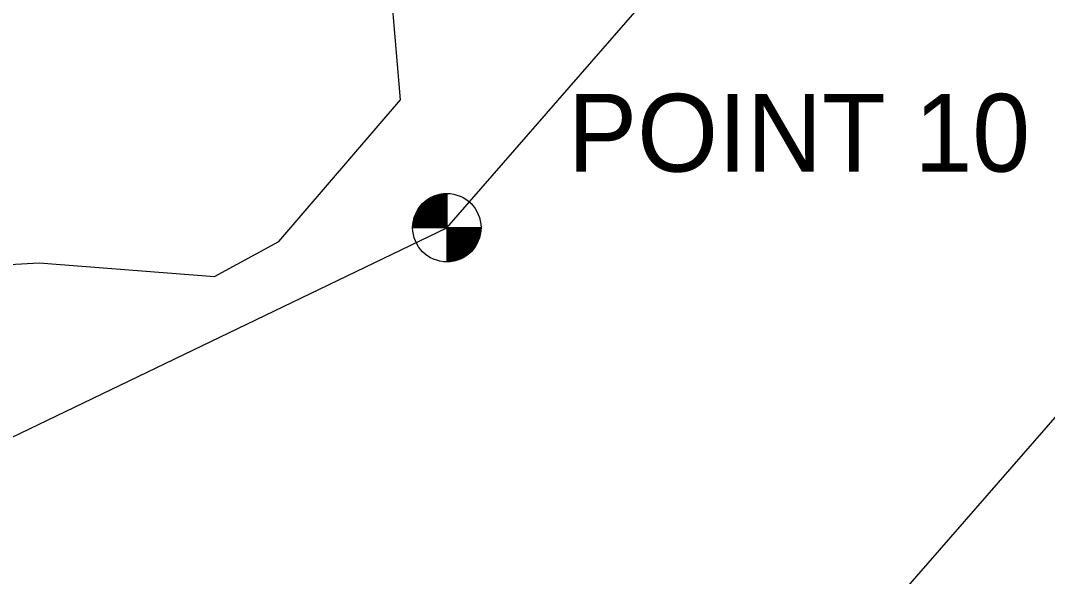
# Model space of a CAD drawing. Extents: x 2091245 to 2092168, y 863656 to 864307.
# Drawn here: x 2091682 to 2091734.8, y 863917.6 to 863946.2 of the extents above; entities that cross this region are included whole.
import ezdxf

# ---------------------------------------------------------------- set-up
doc = ezdxf.new("R2010")
doc.units = 0
for name, color, linetype in [('Exist Hydro Jurisdictional Stream or Body of Water', 7, 'Continuous'), ('Exist Hydrographic Top of Bank', 7, 'Continuous'), ('Prop Boundary Buffer Zone 1', 7, 'Continuous'), ('Prop Boundary Buffer Zone 2', 7, 'Continuous'), ('Scratch_Level_6', 7, 'Continuous')]:
    doc.layers.add(name, color=color, linetype=linetype)

msp = doc.modelspace()

# ---------------------------------------------------------------- linework, layer by layer
at = {"layer": 'Exist Hydro Jurisdictional Stream or Body of Water'}
msp.add_lwpolyline([(2091673.038, 863927.911), (2091672.627, 863930.924), (2091675.297, 863933.324), (2091682.95, 863933.761), (2091691.963, 863933.051), (2091695.28, 863934.846), (2091701.524, 863942.139), (2091700.79, 863950.834), (2091700.072, 863952.463), (2091701.052, 863960.667), (2091705.84, 863965.844), (2091716.038, 863968.921), (2091730.163, 863972.743), (2091727.795, 863981.975), (2091728.219, 863990.873), (2091752.896, 864007.718), (2091756.927, 864019.571), (2091767.092, 864026.792), (2091774.676, 864028.045), (2091779.207, 864034.48), (2091785.465, 864035.877), (2091790.325, 864037.563), (2091800.277, 864042.765), (2091802.985, 864045.288)], dxfattribs=at)
at = {"layer": 'Exist Hydrographic Top of Bank'}
msp.add_lwpolyline([(2091672.3, 863948.34), (2091672.795, 863927.55), (2091675.886, 863922.062), (2091703.915, 863935.563), (2091732.111, 863967.919), (2091742.84, 863995.86), (2091771.423, 864017.904), (2091796.939, 864035.122), (2091802.35, 864043.97), (2091798.347, 864050.35), (2091774.513, 864034.247), (2091751.1, 864019.64), (2091722.53, 863989.28), (2091717.91, 863987.56), (2091701.99, 863966.43)], close=True, dxfattribs=at)
at = {"layer": 'Prop Boundary Buffer Zone 1'}
msp.add_lwpolyline([(2091641.896, 863964.945), (2091642.981, 863919.351), (2091663.555, 863882.824), (2091722.485, 863911.209), (2091758.215, 863952.211), (2091767.828, 863977.246), (2091788.992, 863993.568), (2091819.128, 864013.904), (2091837.639, 864044.171), (2091807.267, 864092.583), (2091758.17, 864059.411), (2091731.919, 864043.033), (2091705.49, 864014.948), (2091699.226, 864012.616), (2091681.482, 863989.064)], close=True, dxfattribs=at)
at = {"layer": 'Prop Boundary Buffer Zone 2'}
msp.add_lwpolyline([(2091688.904, 863895.034), (2091722.485, 863911.209), (2091758.215, 863952.211), (2091767.828, 863977.246), (2091788.992, 863993.568), (2091813.72, 864010.255)], dxfattribs=at)
at = {"layer": 'Scratch_Level_6'}
for p, q in [((2091702.158, 863935.597), (2091703.881, 863937.32)), ((2091702.159, 863935.633), (2091703.845, 863937.319)), ((2091702.16, 863935.563), (2091703.915, 863937.319)), ((2091702.161, 863935.67), (2091703.808, 863937.317)), ((2091702.164, 863935.708), (2091703.77, 863937.314)), ((2091702.167, 863935.748), (2091703.731, 863937.311)), ((2091702.172, 863935.788), (2091703.691, 863937.306)), ((2091702.178, 863935.829), (2091703.649, 863937.3)), ((2091702.185, 863935.871), (2091703.607, 863937.293)), ((2091702.193, 863935.915), (2091703.564, 863937.285)), ((2091702.195, 863935.563), (2091703.915, 863937.283)), ((2091702.203, 863935.96), (2091703.518, 863937.275)), ((2091702.214, 863936.007), (2091703.471, 863937.263)), ((2091702.228, 863936.056), (2091703.422, 863937.25)), ((2091702.23, 863935.563), (2091703.915, 863937.248)), ((2091702.244, 863936.107), (2091703.371, 863937.234)), ((2091702.262, 863936.161), (2091703.317, 863937.216)), ((2091702.266, 863935.563), (2091703.915, 863937.213)), ((2091702.284, 863936.218), (2091703.26, 863937.194)), ((2091702.301, 863935.563), (2091703.915, 863937.177)), ((2091702.31, 863936.279), (2091703.199, 863937.168)), ((2091702.336, 863935.563), (2091703.915, 863937.142)), ((2091702.342, 863936.346), (2091703.132, 863937.136)), ((2091702.372, 863935.563), (2091703.915, 863937.106)), ((2091702.382, 863936.421), (2091703.057, 863937.097)), ((2091702.407, 863935.563), (2091703.915, 863937.071)), ((2091702.434, 863936.509), (2091702.969, 863937.044)), ((2091702.442, 863935.563), (2091703.915, 863937.036)), ((2091702.478, 863935.563), (2091703.915, 863937)), ((2091702.896, 863936.995), (2091703.915, 863935.976)), ((2091702.917, 863937.01), (2091703.915, 863936.012)), ((2091702.938, 863937.024), (2091703.915, 863936.047)), ((2091702.959, 863937.038), (2091703.915, 863936.082)), ((2091702.981, 863937.052), (2091703.915, 863936.118)), ((2091703.003, 863937.065), (2091703.915, 863936.153)), ((2091703.025, 863937.079), (2091703.915, 863936.188)), ((2091703.048, 863937.091), (2091703.915, 863936.224)), ((2091703.07, 863937.104), (2091703.915, 863936.259)), ((2091703.093, 863937.116), (2091703.915, 863936.295)), ((2091703.116, 863937.129), (2091703.915, 863936.33)), ((2091703.14, 863937.14), (2091703.915, 863936.365)), ((2091703.164, 863937.152), (2091703.915, 863936.401)), ((2091703.188, 863937.163), (2091703.915, 863936.436)), ((2091703.213, 863937.174), (2091703.915, 863936.471)), ((2091703.237, 863937.185), (2091703.915, 863936.507)), ((2091703.262, 863937.195), (2091703.915, 863936.542)), ((2091703.288, 863937.205), (2091703.915, 863936.577)), ((2091703.314, 863937.214), (2091703.915, 863936.613)), ((2091703.34, 863937.224), (2091703.915, 863936.648)), ((2091703.366, 863937.233), (2091703.915, 863936.683)), ((2091703.393, 863937.241), (2091703.915, 863936.719)), ((2091703.42, 863937.249), (2091703.915, 863936.754)), ((2091703.447, 863937.257), (2091703.915, 863936.79)), ((2091703.475, 863937.265), (2091703.915, 863936.825)), ((2091703.504, 863937.272), (2091703.915, 863936.86)), ((2091703.532, 863937.278), (2091703.915, 863936.896)), ((2091703.561, 863937.285), (2091703.915, 863936.931)), ((2091703.591, 863937.29), (2091703.915, 863936.966)), ((2091703.621, 863937.296), (2091703.915, 863937.002)), ((2091703.652, 863937.301), (2091703.915, 863937.037)), ((2091703.682, 863937.305), (2091703.915, 863937.072)), ((2091703.714, 863937.309), (2091703.915, 863937.108)), ((2091703.746, 863937.312), (2091703.915, 863937.143)), ((2091703.778, 863937.315), (2091703.915, 863937.178)), ((2091703.811, 863937.317), (2091703.915, 863937.214)), ((2091703.845, 863937.319), (2091703.915, 863937.249)), ((2091703.88, 863937.32), (2091703.915, 863937.284)), ((2091703.914, 863937.321), (2091703.915, 863937.32)), ((2091703.915, 863937.321), (2091703.915, 863933.805)), ((2091702.418, 863936.484), (2091703.339, 863935.563)), ((2091702.432, 863936.505), (2091703.374, 863935.563)), ((2091702.446, 863936.527), (2091703.409, 863935.563)), ((2091702.46, 863936.548), (2091703.445, 863935.563)), ((2091702.474, 863936.569), (2091703.48, 863935.563)), ((2091702.489, 863936.59), (2091703.515, 863935.563)), ((2091702.504, 863936.61), (2091703.551, 863935.563)), ((2091702.513, 863935.563), (2091703.915, 863936.965)), ((2091702.516, 863936.626), (2091702.852, 863936.962)), ((2091702.519, 863936.63), (2091703.586, 863935.563)), ((2091702.534, 863936.65), (2091703.621, 863935.563)), ((2091702.548, 863935.563), (2091703.915, 863936.93)), ((2091702.55, 863936.67), (2091703.657, 863935.563)), ((2091702.566, 863936.689), (2091703.692, 863935.563)), ((2091702.582, 863936.708), (2091703.728, 863935.563)), ((2091702.584, 863935.563), (2091703.915, 863936.894)), ((2091702.599, 863936.727), (2091703.763, 863935.563)), ((2091702.615, 863936.746), (2091703.798, 863935.563)), ((2091702.619, 863935.563), (2091703.915, 863936.859)), ((2091702.632, 863936.764), (2091703.834, 863935.563)), ((2091702.649, 863936.782), (2091703.869, 863935.563)), ((2091702.655, 863935.563), (2091703.915, 863936.824)), ((2091702.667, 863936.8), (2091703.904, 863935.563)), ((2091702.685, 863936.818), (2091703.915, 863935.587)), ((2091702.69, 863935.563), (2091703.915, 863936.788)), ((2091702.703, 863936.835), (2091703.915, 863935.623)), ((2091702.721, 863936.852), (2091703.915, 863935.658)), ((2091702.725, 863935.563), (2091703.915, 863936.753)), ((2091702.739, 863936.869), (2091703.915, 863935.693)), ((2091702.758, 863936.886), (2091703.915, 863935.729)), ((2091702.761, 863935.563), (2091703.915, 863936.718)), ((2091702.777, 863936.902), (2091703.915, 863935.764)), ((2091702.796, 863936.918), (2091703.915, 863935.8)), ((2091702.796, 863935.563), (2091703.915, 863936.682)), ((2091702.816, 863936.934), (2091703.915, 863935.835)), ((2091702.831, 863935.563), (2091703.915, 863936.647)), ((2091702.836, 863936.95), (2091703.915, 863935.87)), ((2091702.856, 863936.965), (2091703.915, 863935.906)), ((2091702.867, 863935.563), (2091703.915, 863936.612)), ((2091702.876, 863936.98), (2091703.915, 863935.941)), ((2091702.902, 863935.563), (2091703.915, 863936.576)), ((2091702.937, 863935.563), (2091703.915, 863936.541)), ((2091702.973, 863935.563), (2091703.915, 863936.505)), ((2091703.008, 863935.563), (2091703.915, 863936.47)), ((2091702.202, 863935.957), (2091702.596, 863935.563)), ((2091702.209, 863935.985), (2091702.631, 863935.563)), ((2091702.216, 863936.014), (2091702.667, 863935.563)), ((2091702.224, 863936.041), (2091702.702, 863935.563)), ((2091702.232, 863936.069), (2091702.738, 863935.563)), ((2091702.24, 863936.096), (2091702.773, 863935.563)), ((2091702.249, 863936.122), (2091702.808, 863935.563)), ((2091702.258, 863936.149), (2091702.844, 863935.563)), ((2091702.267, 863936.175), (2091702.879, 863935.563)), ((2091702.277, 863936.2), (2091702.914, 863935.563)), ((2091702.287, 863936.225), (2091702.95, 863935.563)), ((2091702.298, 863936.25), (2091702.985, 863935.563)), ((2091702.308, 863936.275), (2091703.02, 863935.563)), ((2091702.319, 863936.299), (2091703.056, 863935.563)), ((2091702.331, 863936.323), (2091703.091, 863935.563)), ((2091702.342, 863936.347), (2091703.126, 863935.563)), ((2091702.354, 863936.371), (2091703.162, 863935.563)), ((2091702.366, 863936.394), (2091703.197, 863935.563)), ((2091702.379, 863936.417), (2091703.233, 863935.563)), ((2091702.392, 863936.439), (2091703.268, 863935.563)), ((2091702.405, 863936.462), (2091703.303, 863935.563)), ((2091703.043, 863935.563), (2091703.915, 863936.435)), ((2091703.079, 863935.563), (2091703.915, 863936.399)), ((2091703.114, 863935.563), (2091703.915, 863936.364)), ((2091703.15, 863935.563), (2091703.915, 863936.329)), ((2091703.185, 863935.563), (2091703.915, 863936.293)), ((2091703.22, 863935.563), (2091703.915, 863936.258)), ((2091703.256, 863935.563), (2091703.915, 863936.223)), ((2091703.291, 863935.563), (2091703.915, 863936.187)), ((2091703.326, 863935.563), (2091703.915, 863936.152)), ((2091703.362, 863935.563), (2091703.915, 863936.117)), ((2091703.397, 863935.563), (2091703.915, 863936.081)), ((2091703.432, 863935.563), (2091703.915, 863936.046)), ((2091703.468, 863935.563), (2091703.915, 863936.01)), ((2091703.503, 863935.563), (2091703.915, 863935.975)), ((2091703.538, 863935.563), (2091703.915, 863935.94)), ((2091705.673, 863935.563), (2091702.157, 863935.563)), ((2091702.158, 863935.612), (2091702.207, 863935.563)), ((2091702.158, 863935.577), (2091702.172, 863935.563)), ((2091702.16, 863935.646), (2091702.243, 863935.563)), ((2091702.162, 863935.679), (2091702.278, 863935.563)), ((2091702.164, 863935.712), (2091702.313, 863935.563)), ((2091702.167, 863935.745), (2091702.349, 863935.563)), ((2091702.17, 863935.776), (2091702.384, 863935.563)), ((2091702.175, 863935.808), (2091702.419, 863935.563)), ((2091702.179, 863935.838), (2091702.455, 863935.563)), ((2091702.184, 863935.869), (2091702.49, 863935.563)), ((2091702.19, 863935.899), (2091702.525, 863935.563)), ((2091702.196, 863935.928), (2091702.561, 863935.563)), ((2091703.574, 863935.563), (2091703.915, 863935.904)), ((2091703.609, 863935.563), (2091703.915, 863935.869)), ((2091703.644, 863935.563), (2091703.915, 863935.834)), ((2091703.68, 863935.563), (2091703.915, 863935.798)), ((2091703.715, 863935.563), (2091703.915, 863935.763)), ((2091703.751, 863935.563), (2091703.915, 863935.728)), ((2091703.786, 863935.563), (2091703.915, 863935.692)), ((2091703.821, 863935.563), (2091703.915, 863935.657)), ((2091703.857, 863935.563), (2091703.915, 863935.622)), ((2091703.892, 863935.563), (2091703.915, 863935.586)), ((2091703.915, 863935.528), (2091703.95, 863935.563)), ((2091703.915, 863935.493), (2091703.985, 863935.563)), ((2091703.915, 863935.458), (2091704.02, 863935.563)), ((2091703.915, 863935.422), (2091704.056, 863935.563)), ((2091703.915, 863935.387), (2091704.091, 863935.563)), ((2091703.915, 863935.352), (2091704.126, 863935.563)), ((2091703.915, 863935.316), (2091704.162, 863935.563)), ((2091703.915, 863935.281), (2091704.197, 863935.563)), ((2091703.915, 863935.246), (2091704.233, 863935.563)), ((2091703.915, 863935.21), (2091704.268, 863935.563)), ((2091703.915, 863935.175), (2091704.303, 863935.563)), ((2091703.915, 863935.14), (2091704.339, 863935.563)), ((2091703.915, 863935.104), (2091704.374, 863935.563)), ((2091703.915, 863935.069), (2091704.409, 863935.563)), ((2091703.915, 863935.033), (2091704.445, 863935.563)), ((2091703.915, 863934.998), (2091704.48, 863935.563)), ((2091703.915, 863934.963), (2091704.515, 863935.563)), ((2091703.915, 863934.927), (2091704.551, 863935.563)), ((2091703.915, 863934.892), (2091704.586, 863935.563)), ((2091703.915, 863934.857), (2091704.621, 863935.563)), ((2091703.915, 863934.821), (2091704.657, 863935.563)), ((2091703.915, 863934.786), (2091704.692, 863935.563)), ((2091703.915, 863934.751), (2091704.728, 863935.563)), ((2091703.915, 863934.715), (2091704.763, 863935.563)), ((2091703.915, 863934.68), (2091704.798, 863935.563)), ((2091703.915, 863934.645), (2091704.834, 863935.563)), ((2091703.915, 863934.609), (2091704.869, 863935.563)), ((2091703.915, 863934.574), (2091704.904, 863935.563)), ((2091703.915, 863934.539), (2091704.94, 863935.563)), ((2091703.915, 863934.503), (2091704.975, 863935.563)), ((2091703.915, 863934.468), (2091705.01, 863935.563)), ((2091703.915, 863934.432), (2091705.046, 863935.563)), ((2091703.915, 863934.397), (2091705.081, 863935.563)), ((2091703.915, 863934.362), (2091705.116, 863935.563)), ((2091703.915, 863934.326), (2091705.152, 863935.563)), ((2091703.915, 863934.291), (2091705.187, 863935.563)), ((2091703.915, 863934.256), (2091705.223, 863935.563)), ((2091703.915, 863934.22), (2091705.258, 863935.563)), ((2091703.915, 863934.185), (2091705.293, 863935.563)), ((2091703.915, 863934.15), (2091705.329, 863935.563)), ((2091703.915, 863934.114), (2091705.364, 863935.563)), ((2091703.915, 863934.079), (2091705.399, 863935.563)), ((2091703.915, 863934.044), (2091705.435, 863935.563)), ((2091703.915, 863934.008), (2091705.47, 863935.563)), ((2091703.915, 863933.973), (2091705.505, 863935.563)), ((2091703.915, 863933.937), (2091705.541, 863935.563)), ((2091703.915, 863933.902), (2091705.576, 863935.563)), ((2091703.915, 863933.867), (2091705.611, 863935.563)), ((2091703.915, 863933.831), (2091705.647, 863935.563)), ((2091703.915, 863935.558), (2091705.155, 863934.318)), ((2091703.915, 863935.523), (2091705.138, 863934.3)), ((2091703.915, 863935.487), (2091705.119, 863934.283)), ((2091703.915, 863935.452), (2091705.101, 863934.266)), ((2091703.915, 863935.417), (2091705.083, 863934.249)), ((2091703.925, 863933.805), (2091705.673, 863935.554)), ((2091703.945, 863935.563), (2091705.173, 863934.335)), ((2091703.96, 863933.806), (2091705.672, 863935.518)), ((2091703.981, 863935.563), (2091705.19, 863934.353)), ((2091703.997, 863933.807), (2091705.671, 863935.481)), ((2091704.016, 863935.563), (2091705.207, 863934.372)), ((2091704.035, 863933.809), (2091705.669, 863935.443)), ((2091704.052, 863935.563), (2091705.224, 863934.39)), ((2091704.087, 863935.563), (2091705.241, 863934.409)), ((2091704.122, 863935.563), (2091705.257, 863934.428)), ((2091704.158, 863935.563), (2091705.273, 863934.447)), ((2091704.193, 863935.563), (2091705.289, 863934.467)), ((2091704.228, 863935.563), (2091705.305, 863934.487)), ((2091704.264, 863935.563), (2091705.32, 863934.507)), ((2091704.299, 863935.563), (2091705.335, 863934.527)), ((2091704.334, 863935.563), (2091705.35, 863934.548)), ((2091704.37, 863935.563), (2091705.364, 863934.568)), ((2091704.405, 863935.563), (2091705.379, 863934.59)), ((2091704.44, 863935.563), (2091705.393, 863934.611)), ((2091704.476, 863935.563), (2091705.406, 863934.632)), ((2091704.511, 863935.563), (2091705.42, 863934.654)), ((2091704.547, 863935.563), (2091705.433, 863934.677)), ((2091704.582, 863935.563), (2091705.446, 863934.699)), ((2091704.617, 863935.563), (2091705.458, 863934.722)), ((2091704.653, 863935.563), (2091705.471, 863934.745)), ((2091704.688, 863935.563), (2091705.483, 863934.768)), ((2091704.723, 863935.563), (2091705.495, 863934.792)), ((2091704.759, 863935.563), (2091705.506, 863934.816)), ((2091704.794, 863935.563), (2091705.517, 863934.84)), ((2091704.829, 863935.563), (2091705.528, 863934.864)), ((2091704.865, 863935.563), (2091705.539, 863934.889)), ((2091704.9, 863935.563), (2091705.549, 863934.914)), ((2091704.935, 863935.563), (2091705.559, 863934.94)), ((2091704.971, 863935.563), (2091705.568, 863934.966)), ((2091705.006, 863935.563), (2091705.577, 863934.992)), ((2091705.042, 863935.563), (2091705.586, 863935.018)), ((2091705.077, 863935.563), (2091705.595, 863935.045)), ((2091705.112, 863935.563), (2091705.603, 863935.072)), ((2091705.148, 863935.563), (2091705.611, 863935.1)), ((2091705.183, 863935.563), (2091705.618, 863935.128)), ((2091705.218, 863935.563), (2091705.625, 863935.156)), ((2091705.254, 863935.563), (2091705.632, 863935.185)), ((2091705.289, 863935.563), (2091705.638, 863935.214)), ((2091705.324, 863935.563), (2091705.644, 863935.244)), ((2091705.36, 863935.563), (2091705.649, 863935.274)), ((2091705.395, 863935.563), (2091705.654, 863935.304)), ((2091705.43, 863935.563), (2091705.658, 863935.335)), ((2091705.466, 863935.563), (2091705.662, 863935.367)), ((2091705.501, 863935.563), (2091705.665, 863935.399)), ((2091705.536, 863935.563), (2091705.668, 863935.432)), ((2091705.572, 863935.563), (2091705.67, 863935.465)), ((2091705.607, 863935.563), (2091705.672, 863935.499)), ((2091705.643, 863935.563), (2091705.673, 863935.533)), ((2091703.915, 863935.381), (2091705.064, 863934.233)), ((2091703.915, 863935.346), (2091705.045, 863934.216)), ((2091703.915, 863935.31), (2091705.025, 863934.2)), ((2091703.915, 863935.275), (2091705.006, 863934.185)), ((2091703.915, 863935.24), (2091704.986, 863934.169)), ((2091703.915, 863935.204), (2091704.966, 863934.154)), ((2091703.915, 863935.169), (2091704.945, 863934.139)), ((2091703.915, 863935.134), (2091704.925, 863934.124)), ((2091703.915, 863935.098), (2091704.904, 863934.11)), ((2091703.915, 863935.063), (2091704.883, 863934.096)), ((2091703.915, 863935.028), (2091704.861, 863934.082)), ((2091703.915, 863934.992), (2091704.839, 863934.068)), ((2091703.915, 863934.957), (2091704.818, 863934.055)), ((2091703.915, 863934.922), (2091704.795, 863934.042)), ((2091703.915, 863934.886), (2091704.773, 863934.029)), ((2091704.073, 863933.813), (2091705.666, 863935.405)), ((2091704.112, 863933.817), (2091705.662, 863935.366)), ((2091704.153, 863933.821), (2091705.657, 863935.325)), ((2091704.194, 863933.828), (2091705.651, 863935.284)), ((2091704.237, 863933.835), (2091705.643, 863935.241)), ((2091704.281, 863933.844), (2091705.634, 863935.197)), ((2091704.327, 863933.854), (2091705.624, 863935.151)), ((2091704.374, 863933.866), (2091705.612, 863935.104)), ((2091704.424, 863933.881), (2091705.598, 863935.054)), ((2091704.476, 863933.897), (2091705.581, 863935.002)), ((2091704.531, 863933.917), (2091705.562, 863934.948)), ((2091704.589, 863933.94), (2091705.539, 863934.889)), ((2091703.915, 863934.851), (2091704.75, 863934.016)), ((2091703.915, 863934.815), (2091704.727, 863934.004)), ((2091703.915, 863934.78), (2091704.703, 863933.992)), ((2091703.915, 863934.745), (2091704.68, 863933.98)), ((2091703.915, 863934.709), (2091704.656, 863933.969)), ((2091703.915, 863934.674), (2091704.631, 863933.958)), ((2091703.915, 863934.639), (2091704.607, 863933.947)), ((2091703.915, 863934.603), (2091704.582, 863933.937)), ((2091703.915, 863934.568), (2091704.557, 863933.927)), ((2091703.915, 863934.533), (2091704.531, 863933.917)), ((2091703.915, 863934.497), (2091704.505, 863933.907)), ((2091703.915, 863934.462), (2091704.479, 863933.898)), ((2091703.915, 863934.427), (2091704.452, 863933.889)), ((2091703.915, 863934.391), (2091704.425, 863933.881)), ((2091703.915, 863934.356), (2091704.398, 863933.873)), ((2091704.652, 863933.967), (2091705.511, 863934.826)), ((2091704.721, 863934.001), (2091705.477, 863934.757)), ((2091704.8, 863934.044), (2091705.434, 863934.679)), ((2091704.894, 863934.104), (2091705.375, 863934.584)), ((2091705.033, 863934.207), (2091705.272, 863934.446)), ((2091703.915, 863934.32), (2091704.37, 863933.865)), ((2091703.915, 863934.285), (2091704.342, 863933.858)), ((2091703.915, 863934.25), (2091704.314, 863933.851)), ((2091703.915, 863934.214), (2091704.285, 863933.845)), ((2091703.915, 863934.179), (2091704.256, 863933.839)), ((2091703.915, 863934.144), (2091704.226, 863933.833)), ((2091703.915, 863934.108), (2091704.196, 863933.828)), ((2091703.915, 863934.073), (2091704.165, 863933.823)), ((2091703.915, 863934.038), (2091704.134, 863933.819)), ((2091703.915, 863934.002), (2091704.102, 863933.815)), ((2091703.915, 863933.967), (2091704.07, 863933.812)), ((2091703.915, 863933.932), (2091704.037, 863933.81)), ((2091703.915, 863933.896), (2091704.004, 863933.808)), ((2091703.915, 863933.861), (2091703.97, 863933.806)), ((2091703.915, 863933.826), (2091703.935, 863933.806))]:
    msp.add_line(p, q, dxfattribs=at)
msp.add_circle((2091703.915, 863935.563), 1.758, dxfattribs=at)

# ---------------------------------------------------------------- texts
msp.add_text('POINT 10', height=4, dxfattribs=at).set_placement((2091710.135, 863938.445))

doc.saveas('drawing.dxf')
